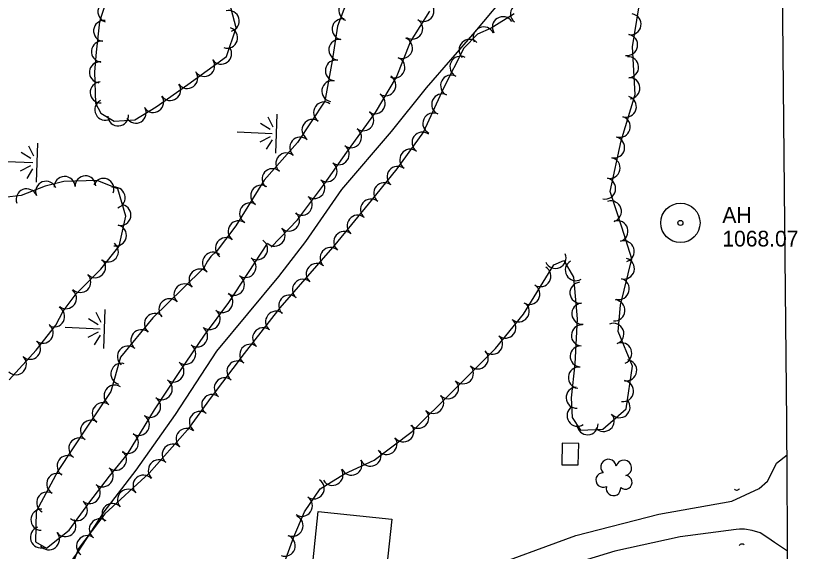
# Model space of a CAD drawing. Extents: x 296487 to 298842, y 31545 to 32791.
# Drawn here: x 297435.1 to 297733.1, y 32035.7 to 32240 of the extents above; entities that cross this region are included whole.
import ezdxf

# ---------------------------------------------------------------- set-up
doc = ezdxf.new("R2010")
doc.units = 0
for name, color, linetype in [('Level 11', 7, 'Continuous'), ('Level 12', 7, 'Continuous'), ('Level 15', 7, 'Continuous'), ('Level 17', 7, 'Continuous'), ('Level 18', 7, 'Continuous'), ('Level 19', 7, 'Continuous'), ('Level 6', 7, 'Continuous')]:
    doc.layers.add(name, color=color, linetype=linetype)

msp = doc.modelspace()

# ---------------------------------------------------------------- linework, layer by layer
at = {"layer": 'Level 11'}
msp.add_lwpolyline([(297732.45, 31749.54), (297732.24, 31791.84), (297732.13, 31829.29), (297731.83, 31872.75), (297730.81, 31924.68), (297730.53, 31968.01), (297729.53, 32021.42), (297729.12, 32084.97), (297728.52, 32147.82), (297727.87, 32212.59), (297727.19, 32277.97), (297726.38, 32352.97), (297725.93, 32414.91), (297724.99, 32486.15), (297724.55, 32554.59), (297723.53, 32621.52), (297723.38, 32689.57), (297722.58, 32747.62), (297722.25, 32760.6)], dxfattribs=at)
at = {"layer": 'Level 12'}
for points in [[(297649.6, 32068.62), (297649.76, 32076.86), (297643.48, 32076.98), (297643.33, 32068.74)], [(297547.6, 32023.83), (297550.48, 32050.93), (297578.49, 32047.96), (297575.62, 32020.86)]]:
    msp.add_lwpolyline(points, close=True, dxfattribs=at)
at = {"layer": 'Level 15'}
for centre, radius, start, end in [((297709.98, 32060.27), 1.23, 225.4723, 331.7119), ((297712, 32037.34), 1.16, 42.2496, 148.4892)]:
    msp.add_arc(centre, radius, start, end, dxfattribs=at)
at = {"layer": 'Level 17'}
for points in [[(297623.99, 32250.43), (297610.13, 32233.83), (297591.62, 32212.39), (297578.2, 32195.81), (297559.31, 32173.69), (297545.59, 32153.8), (297535.31, 32140.44), (297511.71, 32112.03), (297495.92, 32087.9), (297480.91, 32066.68), (297468.73, 32050.81), (297458.54, 32035.07), (297449.94, 32023.36), (297435.5, 32005.16), (297419.75, 31981.41), (297405.85, 31956.85), (297394.34, 31937.67), (297382.2, 31916.55), (297361.04, 31874.71), (297352.86, 31857.17), (297348.71, 31848.4), (297345.52, 31842.04), (297344.4, 31839.03)], [(297611.92, 32028.26), (297648.67, 32041.76), (297680.38, 32049.82), (297708.11, 32054.77), (297718.61, 32059.67), (297721.81, 32062.4), (297722.67, 32064.17), (297725.23, 32069.36), (297729.2, 32072.49)], [(297729.44, 32035.81), (297724.4, 32039.11), (297721.87, 32040.79), (297718.97, 32042.8), (297715.9, 32043.7), (297713, 32044.12), (297711.06, 32044.15), (297709.77, 32044.05), (297688.43, 32041.23), (297663.57, 32035.71), (297632.32, 32026.27), (297611.12, 32017.74), (297577.29, 32002.8), (297568.14, 31996.83), (297564.66, 31993.74), (297563.14, 31992.11), (297558.04, 31980.8), (297558.08, 31976.14), (297557.89, 31972.64), (297557.78, 31968.11), (297557.58, 31965.36)]]:
    msp.add_lwpolyline(points, dxfattribs=at)
at = {"layer": 'Level 18'}
for points in [[(297465.56, 32206.62), (297467.57, 32202.81), (297472.61, 32199.67), (297480.52, 32200.23), (297488.62, 32205.21), (297500.74, 32213.74), (297515.51, 32224.33), (297519.22, 32235.33), (297516.59, 32244.9), (297500.87, 32253.12), (297481.11, 32255.26), (297470.47, 32248.42), (297467.03, 32237.62), (297465.83, 32226.06), (297465.08, 32218.51), (297465.56, 32206.62)], [(297564.67, 32254.13), (297557.79, 32235.94), (297555.71, 32222.76), (297552.99, 32207.28), (297542.55, 32191.62), (297529.88, 32177.22), (297519.08, 32159.87), (297511.21, 32149.38)], [(297537.12, 32030.07), (297541.1, 32041.21), (297545.23, 32050.77), (297551.2, 32059.56), (297560.5, 32065.19), (297571.74, 32070.47), (297586.24, 32081.33), (297602.01, 32096.98), (297618.07, 32113.09), (297628.7, 32126.13), (297640.27, 32144.97), (297644.07, 32146.62), (297647.78, 32140.22), (297649.22, 32124.39), (297648.27, 32107.17), (297646.88, 32094.25), (297647.23, 32086.78), (297650.39, 32081.93), (297658.92, 32082.31), (297667.82, 32090.02), (297670.22, 32106.31), (297664.87, 32119.57), (297665.67, 32129.59), (297670.08, 32147.17), (297666.27, 32159.27), (297661.74, 32172.88), (297665.97, 32192.18), (297671.34, 32209.83), (297670.25, 32228.08), (297672.66, 32242.96)], [(297625.12, 32240.7), (297616.41, 32235.22), (297611.15, 32232.85), (297605.92, 32227.61), (297598.25, 32212.26), (297590.54, 32195.59), (297580.41, 32181.49), (297570.67, 32169.45), (297556.76, 32152.58), (297535.87, 32128.56), (297522.19, 32111.09), (297509.57, 32094.44), (297500.55, 32082.07), (297485.94, 32065.55), (297469.04, 32050.05), (297458.99, 32036.76), (297453.15, 32021.32), (297448.73, 32007.23), (297439.07, 31989.61), (297427.97, 31975.39)], [(297532.56, 32151.72), (297542.52, 32162.15), (297552.83, 32175.83), (297561.4, 32187.89), (297572.31, 32202.99), (297580.28, 32216.44), (297585.58, 32229.97), (297593.01, 32241.64)], [(297432.6, 32101.13), (297442.95, 32112.38), (297450.35, 32121.96), (297453.23, 32127.33), (297458.18, 32133.89), (297467.58, 32143.27), (297474.56, 32152.09), (297477.09, 32163.54), (297474.03, 32173.96), (297466.21, 32177.11), (297453.41, 32176.73), (297446.29, 32174.92), (297437.12, 32171.35), (297426.24, 32170.09)], [(297511.51, 32149.98), (297509.53, 32148.07), (297508.17, 32146.4), (297506.79, 32143.79), (297499, 32136.1), (297487.41, 32124.76), (297475.02, 32109.78), (297471.36, 32096.68), (297462.44, 32083.38), (297451.33, 32066.56), (297442.88, 32050.83), (297442.64, 32039.28), (297446.83, 32036.91), (297455.43, 32043.74), (297462.92, 32054.06), (297470.92, 32064.34), (297477.72, 32072.77), (297488.03, 32089.63), (297497.73, 32104.33), (297507.08, 32118.12), (297516.39, 32130.63), (297531.09, 32153.12)]]:
    msp.add_lwpolyline(points, dxfattribs=at)
for centre, radius, start, end in [((297470.43, 32241.44), 3.98, 72.3606, 252.3453), ((297562.28, 32241.9), 3.99, 69.2779, 249.2625), ((297590.6, 32241.74), 3.99, 237.5168, 57.5015), ((297627.78, 32240.67), 4.01, 51.1953, 231.18), ((297516.36, 32237.91), 3.98, 285.3847, 105.3694), ((297620.85, 32235.53), 4.01, 32.2114, 212.1961), ((297669.52, 32236.66), 4.01, 260.8022, 80.7869), ((297468.76, 32234.14), 3.98, 84.0895, 264.0742), ((297559.72, 32234.8), 3.99, 81.0368, 261.0215), ((297586.31, 32235.01), 3.99, 237.5168, 57.5015), ((297515.75, 32231.54), 3.98, 251.351, 71.3357), ((297613.54, 32231.62), 4.01, 24.2857, 204.2703), ((297558.48, 32226.92), 3.99, 81.0368, 261.0215), ((297582.41, 32227.62), 3.99, 248.6273, 68.612), ((297608.15, 32226.88), 4.01, 45.0186, 225.0033), ((297668.24, 32228.75), 4.01, 260.8022, 80.7869), ((297467.94, 32226.23), 3.98, 84.0895, 264.0742), ((297513.45, 32225.41), 3.98, 215.656, 35.6407), ((297604.69, 32220.46), 4.01, 63.462, 243.4467), ((297668.61, 32220.29), 4.01, 273.4111, 93.3958), ((297467.15, 32218.33), 3.98, 84.3023, 264.287), ((297506.98, 32220.78), 3.98, 215.656, 35.6407), ((297557.17, 32219.01), 3.99, 80.0371, 260.0217), ((297579.5, 32220.19), 3.99, 248.6273, 68.612), ((297500.52, 32216.15), 3.98, 215.656, 35.6407), ((297576.05, 32213.4), 3.99, 239.3662, 59.3509), ((297601.11, 32213.29), 4.01, 63.462, 243.4467), ((297669.09, 32212.29), 4.01, 273.4111, 93.3958), ((297467.48, 32210.68), 3.98, 92.3497, 272.3344), ((297494.04, 32211.57), 3.98, 215.1349, 35.1196), ((297555.79, 32211.14), 3.99, 80.0371, 260.0217), ((297571.98, 32206.53), 3.99, 239.3662, 59.3509), ((297597.71, 32206.1), 4.01, 65.2038, 245.1884), ((297469.25, 32204.07), 3.98, 117.708, 297.6927), ((297487.54, 32207), 3.98, 215.1349, 35.1196), ((297552.68, 32203.05), 3.99, 56.3227, 236.3073), ((297667.75, 32205.25), 4.01, 253.0803, 73.065), ((297480.88, 32202.9), 3.98, 211.5907, 31.5754), ((297474.14, 32201.87), 3.98, 184.0809, 4.0656), ((297567.63, 32200.07), 3.99, 234.1535, 54.1382), ((297594.35, 32198.82), 4.01, 65.2038, 245.1884), ((297665.42, 32197.59), 4.01, 253.0803, 73.065), ((297548.25, 32196.41), 3.99, 56.3227, 236.3073), ((297562.95, 32193.6), 3.99, 234.1535, 54.1382), ((297590.22, 32191.54), 4.01, 54.3093, 234.2939), ((297543.56, 32189.61), 3.99, 48.6689, 228.6535), ((297663.27, 32189.7), 4.01, 257.6515, 77.6362), ((297558.28, 32187.11), 3.99, 234.6213, 54.6059), ((297585.54, 32185.03), 4.01, 54.3093, 234.2939), ((297538.29, 32183.62), 3.99, 48.6689, 228.6535), ((297661.56, 32181.87), 4.01, 257.6515, 77.6362), ((297553.66, 32180.6), 3.99, 234.6213, 54.6059), ((297533.02, 32177.62), 3.99, 48.6689, 228.6535), ((297580.69, 32178.5), 4.01, 51.0093, 230.994), ((297446.69, 32172.84), 3.99, 21.3158, 201.3005), ((297453.72, 32174.65), 3.99, 1.7167, 181.7014), ((297461.7, 32174.89), 3.99, 1.7167, 181.7014), ((297468.58, 32173.9), 3.99, 338.0701, 158.0547), ((297548.99, 32174.2), 3.99, 232.9826, 52.9673), ((297659.84, 32174.04), 4.01, 257.6515, 77.6362), ((297439.26, 32169.94), 3.99, 21.3158, 201.3005), ((297472.86, 32170.55), 3.99, 286.3698, 106.3545), ((297528.69, 32171.35), 3.99, 58.103, 238.0876), ((297575.65, 32172.27), 4.01, 51.0093, 230.994), ((297544.18, 32167.83), 3.99, 232.9826, 52.9673), ((297475.04, 32163.93), 3.99, 257.5367, 77.5213), ((297524.47, 32164.58), 3.99, 58.103, 238.0876), ((297570.57, 32166.04), 4.01, 50.51, 230.4947), ((297662.05, 32165.3), 4.01, 288.4161, 108.4008), ((297539.31, 32161.82), 3.99, 226.3394, 46.324), ((297565.48, 32159.86), 4.01, 50.51, 230.4947), ((297664.55, 32157.73), 4.01, 287.4729, 107.4576), ((297473.32, 32156.14), 3.99, 257.5367, 77.5213), ((297520.07, 32157.71), 3.99, 53.1124, 233.0971), ((297533.8, 32156.05), 3.99, 226.3394, 46.324), ((297560.38, 32153.67), 4.01, 50.51, 230.4947), ((297470.26, 32150.02), 3.99, 231.6675, 51.6521), ((297515.27, 32151.32), 3.99, 53.1124, 233.0971), ((297527.11, 32150.9), 4.04, 236.8429, 56.8276), ((297666.96, 32150.08), 4.01, 287.4729, 107.4576), ((297555.15, 32147.53), 4.01, 48.999, 228.9837), ((297465.39, 32144.03), 3.99, 224.9588, 44.9435), ((297510.36, 32145.74), 4.04, 50.8287, 230.8133), ((297522.7, 32144.14), 4.04, 236.8429, 56.8276), ((297640.95, 32147.55), 4.01, 203.4676, 23.4523), ((297667, 32143.51), 4.01, 255.9285, 75.9131), ((297549.89, 32141.48), 4.01, 48.999, 228.9837), ((297635.15, 32140.64), 4.01, 238.4594, 58.4441), ((297648.65, 32142.9), 4.01, 120.1542, 300.1389), ((297459.74, 32138.39), 3.99, 224.9588, 44.9435), ((297505.25, 32139.3), 4.04, 44.5858, 224.5705), ((297518.28, 32137.38), 4.04, 236.8429, 56.8276), ((297544.63, 32135.43), 4.01, 48.999, 228.9837), ((297650.43, 32134.3), 4.01, 95.1926, 275.1773), ((297665.05, 32135.73), 4.01, 255.9285, 75.9131), ((297454.29, 32132.2), 3.99, 232.9551, 52.9398), ((297499.49, 32133.63), 4.04, 44.3979, 224.3826), ((297630.96, 32133.81), 4.01, 238.4594, 58.4441), ((297493.72, 32127.99), 4.04, 44.3979, 224.3826), ((297513.87, 32130.78), 4.04, 233.3589, 53.3436), ((297539.37, 32129.39), 4.01, 48.999, 228.9837), ((297626.89, 32127.23), 4.01, 230.8314, 50.816), ((297651.15, 32126.32), 4.01, 95.1926, 275.1773), ((297663.4, 32127.56), 4.01, 265.4337, 85.4184), ((297449.76, 32125.27), 3.99, 241.7808, 61.7655), ((297488.21, 32122.41), 4.04, 50.4006, 230.3853), ((297509.05, 32124.3), 4.04, 233.3589, 53.3436), ((297534.38, 32123.26), 4.01, 51.9383, 231.923), ((297621.83, 32121.02), 4.01, 230.8314, 50.816), ((297445.43, 32119.01), 3.99, 232.3245, 52.3092), ((297483.06, 32116.19), 4.04, 50.4006, 230.3853), ((297504.25, 32117.7), 4.04, 235.8779, 55.8625), ((297529.44, 32116.95), 4.01, 51.9383, 231.923), ((297650.97, 32118.01), 4.01, 86.8426, 266.8273), ((297662.98, 32118.63), 4.01, 292.0189, 112.0036), ((297616.77, 32114.81), 4.01, 230.8314, 50.816), ((297440.59, 32112.9), 3.99, 227.4091, 47.3937), ((297499.72, 32111.02), 4.04, 235.8779, 55.8625), ((297524.5, 32110.64), 4.01, 51.9383, 231.923), ((297650.53, 32110.01), 4.01, 86.8426, 266.8273), ((297665.99, 32111.2), 4.01, 292.0189, 112.0036), ((297477.91, 32109.97), 4.04, 50.4006, 230.3853), ((297611.29, 32109.25), 4.01, 225.086, 45.0707), ((297435.19, 32107.03), 3.99, 227.4091, 47.3937), ((297519.66, 32104.29), 4.01, 52.829, 232.8137), ((297667.87, 32104.74), 4.01, 261.6016, 81.5863), ((297475.42, 32103.36), 4.04, 74.41, 254.3947), ((297495.19, 32104.3), 4.04, 236.5585, 56.5432), ((297605.63, 32103.58), 4.01, 225.086, 45.0707), ((297649.81, 32101.92), 4.01, 83.8807, 263.8654), ((297490.74, 32097.57), 4.04, 236.5585, 56.5432), ((297514.82, 32097.9), 4.01, 52.829, 232.8137), ((297599.97, 32097.91), 4.01, 224.798, 44.7827), ((297666.7, 32096.81), 4.01, 261.6016, 81.5863), ((297472.81, 32095.05), 4.04, 56.1717, 236.1564), ((297648.98, 32094.28), 4.01, 92.6822, 272.6669), ((297486.29, 32090.83), 4.04, 236.5585, 56.5432), ((297510.03, 32091.53), 4.01, 53.9498, 233.9344), ((297594.29, 32092.27), 4.01, 224.798, 44.7827), ((297665.34, 32090.65), 4.01, 220.9404, 40.9251), ((297468.31, 32088.34), 4.04, 56.1717, 236.1564), ((297649.32, 32087.41), 4.01, 123.0361, 303.0208), ((297482.04, 32083.88), 4.04, 238.5576, 58.5423), ((297505.32, 32085.05), 4.01, 53.9498, 233.9344), ((297588.6, 32086.62), 4.01, 224.798, 44.7827), ((297659.29, 32085.4), 4.01, 220.9404, 40.9251), ((297463.83, 32081.65), 4.04, 56.55, 236.5347), ((297653.12, 32084.15), 4.01, 182.5499, 2.5346), ((297500.27, 32078.58), 4.01, 48.5092, 228.4939), ((297582.89, 32081.44), 4.01, 216.8459, 36.8306), ((297459.38, 32074.91), 4.04, 56.55, 236.5347), ((297477.82, 32077), 4.04, 238.5576, 58.5423), ((297576.48, 32076.63), 4.01, 216.8459, 36.8306), ((297494.96, 32072.58), 4.01, 48.5092, 228.4939), ((297473.3, 32070.66), 4.04, 231.138, 51.1227), ((297570.38, 32072.14), 4.01, 205.1447, 25.1294), ((297454.93, 32068.18), 4.04, 56.55, 236.5347), ((297489.65, 32066.57), 4.01, 48.5092, 228.4939), ((297563.12, 32068.74), 4.01, 205.1447, 25.1294), ((297661.13, 32067.85), 2.97, 6.0939, 227.3278), ((297666.98, 32067.5), 2.97, 283.7448, 166.718), ((297468.24, 32064.33), 4.04, 232.1064, 52.0911), ((297555.88, 32064.85), 4.01, 211.1657, 31.1504), ((297450.94, 32061.38), 4.04, 61.7662, 241.7509), ((297483.83, 32060.76), 4.01, 42.5226, 222.5072), ((297659.07, 32062.89), 2.78, 89.0648, 296.8378), ((297667.52, 32062.01), 2.61, 228.45, 86.3826), ((297463.28, 32057.96), 4.04, 232.1064, 52.0911), ((297548.74, 32059.69), 4.01, 235.8483, 55.833), ((297663.02, 32059.72), 2.78, 165.7418, 6.7529), ((297447.12, 32054.27), 4.04, 61.7662, 241.7509), ((297477.92, 32055.35), 4.01, 42.5226, 222.5072), ((297458.4, 32051.44), 4.04, 234.0328, 54.0175), ((297544.24, 32053.05), 4.01, 235.8483, 55.833), ((297444.93, 32047.76), 4.04, 88.842, 268.8266), ((297472.01, 32049.93), 4.01, 42.5226, 222.5072), ((297540.66, 32045.47), 4.01, 246.6559, 66.6406), ((297454.04, 32045.34), 4.04, 218.4572, 38.4418), ((297467.15, 32044.08), 4.01, 52.906, 232.8907), ((297444.72, 32041.05), 4.04, 108.842, 288.8266), ((297447.72, 32040.32), 4.04, 218.4572, 38.4418), ((297462.31, 32037.69), 4.01, 52.906, 232.8907), ((297537.69, 32037.89), 4.01, 250.3652, 70.3499)]:
    msp.add_arc(centre, radius, start, end, dxfattribs=at)
at = {"layer": 'Level 19'}
for p, q in [((297531.22, 32201.35), (297533.16, 32197.58)), ((297534.24, 32187.57), (297534.84, 32202.35)), ((297532.18, 32196.52), (297528.43, 32198.87)), ((297519.49, 32195.6), (297532.9, 32195.06)), ((297532.07, 32193.72), (297528.13, 32191.67)), ((297530.72, 32188.98), (297532.96, 32192.58)), ((297439.95, 32190.26), (297441.89, 32186.49)), ((297442.97, 32176.49), (297443.57, 32191.27)), ((297440.91, 32185.43), (297437.16, 32187.79)), ((297428.22, 32184.52), (297441.62, 32183.97)), ((297440.8, 32182.63), (297436.86, 32180.59)), ((297439.45, 32177.9), (297441.69, 32181.49)), ((297465.64, 32126.86), (297467.58, 32123.09)), ((297468.66, 32113.08), (297469.26, 32127.87)), ((297466.6, 32122.03), (297462.85, 32124.39)), ((297453.91, 32121.12), (297467.31, 32120.57)), ((297466.49, 32119.23), (297462.55, 32117.19)), ((297465.14, 32114.49), (297467.38, 32118.09))]:
    msp.add_line(p, q, dxfattribs=at)
at = {"layer": 'Level 6'}
for radius in [7.5, 0.96]:
    msp.add_circle((297688.54, 32160.93), radius, dxfattribs=at)

# ---------------------------------------------------------------- texts
for s, p in [('AH', (297704.54, 32160.93)), ('1068.07', (297704.54, 32151.93))]:
    msp.add_text(s, height=6, dxfattribs=at).set_placement(p)

doc.saveas('drawing.dxf')
